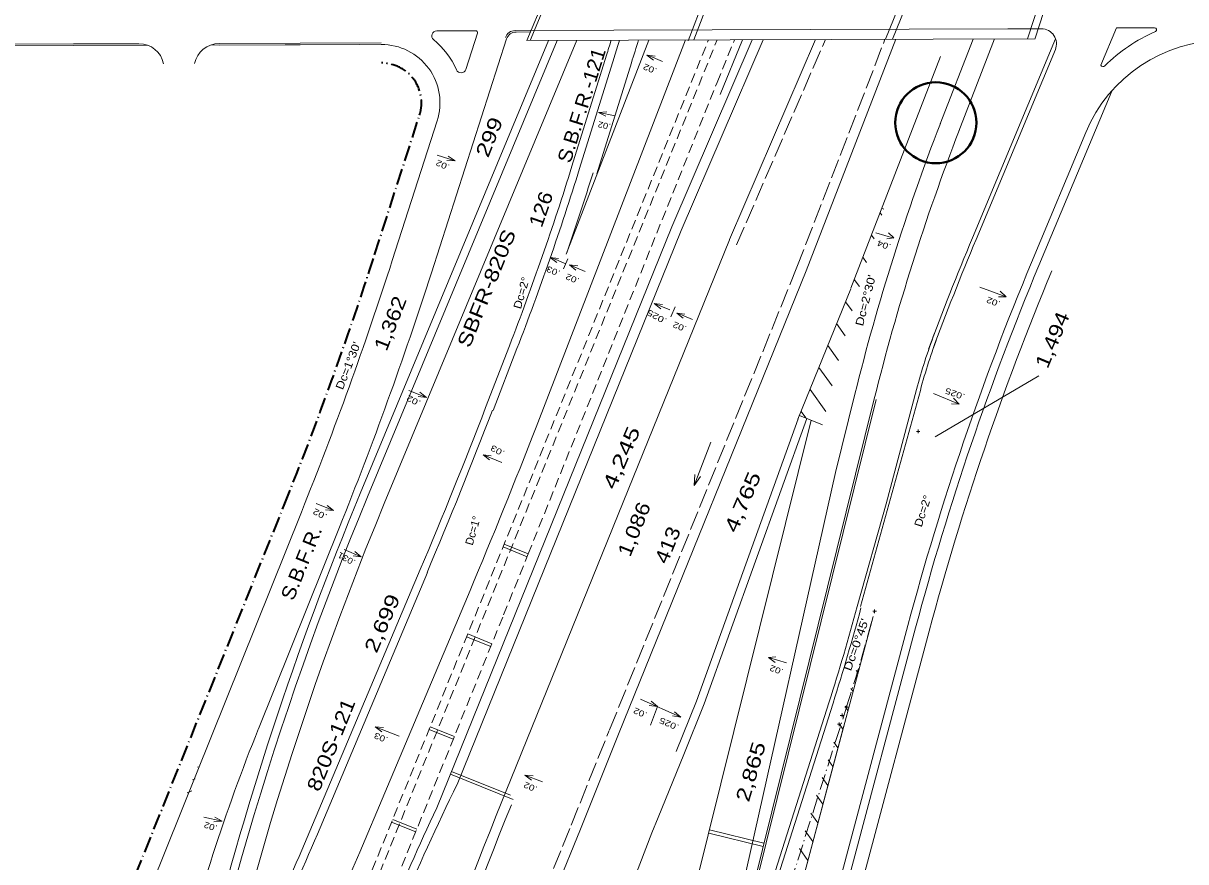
# Model space of a CAD drawing. Extents: x 2354993 to 2372084, y 6966390 to 6990057.
# Drawn here: x 2364225 to 2365387, y 6979642 to 6980481 of the extents above; entities that cross this region are included whole.
import ezdxf

# ---------------------------------------------------------------- set-up
doc = ezdxf.new("R2010")
doc.units = 0
doc.header["$LTSCALE"] = 3.2
for name, pattern in [('DOT_DASHED', [7.7, 5, -1.2, 0.3, -1.2]), ('LONG_DASHED', [7.5, 6, -1.5]), ('MEDIUM_DASHED', [4.5, 3, -1.5])]:
    doc.linetypes.add(name, pattern=pattern)
for name, color, linetype, lineweight in [('1', 7, 'Continuous', 35), ('12', 7, 'Continuous', 13), ('13', 7, 'Continuous', 13), ('14', 7, 'Continuous', 13), ('17', 7, 'Continuous', 13), ('19', 7, 'Continuous', 13), ('23', 7, 'Continuous', 13), ('25', 7, 'Continuous', 13), ('4', 7, 'Continuous', 13), ('5', 7, 'Continuous', 13), ('6', 7, 'Continuous', 13), ('61', 7, 'Continuous', 13), ('7', 7, 'Continuous', 13), ('9', 7, 'Continuous', 13)]:
    doc.layers.add(name, color=color, linetype=linetype, lineweight=lineweight)

msp = doc.modelspace()

# ---------------------------------------------------------------- linework, layer by layer
at = {"layer": '1', "lineweight": 40}
msp.add_circle((2365136.989, 6980381.3), 40.519, dxfattribs=at)
at = {"layer": '12'}
for p, q in [((2364889.34, 6980463.063), (2364934.323, 6980581.712)), ((2364895.069, 6980464.071), (2364938.998, 6980579.939)), ((2365133.691, 6980580.838), (2365086.673, 6980464.691)), ((2365140.767, 6980580.861), (2365093.748, 6980464.714)), ((2365263.831, 6980574.448), (2365228.608, 6980465.09)), ((2365273.39, 6980581.292), (2365235.902, 6980464.902)), ((2364704.438, 6979956.949), (2364728.538, 6979947.192)), ((2364668.081, 6979867.134), (2364692.181, 6979857.378)), ((2364669.206, 6979869.916), (2364693.307, 6979860.159)), ((2364630.558, 6979774.44), (2364654.658, 6979764.684)), ((2364631.683, 6979777.222), (2364655.784, 6979767.465)), ((2364714.411, 6979704.364), (2364651.877, 6979729.644)), ((2364711.823, 6979708.645), (2364653.001, 6979732.425)), ((2364593.035, 6979681.747), (2364617.135, 6979671.991)), ((2364594.16, 6979684.529), (2364618.261, 6979674.773))]:
    msp.add_line(p, q, dxfattribs=at)
at = {"layer": '13'}
for p, q in [((2365036.612, 6980031.444), (2365056.061, 6980109.786)), ((2364922.585, 6979522.917), (2365036.612, 6980031.444))]:
    msp.add_line(p, q, dxfattribs=at)
msp.add_arc((2362792.03, 6980397.361), 1919.859, 325.95112, 337.15034, dxfattribs=at)
at = {"layer": '14'}
msp.add_line((2364895.323, 6980018.418), (2364901.939, 6980027.303), dxfattribs=at)
msp.add_lwpolyline([(2364912.252, 6980061.865), (2364895.323, 6980018.418), (2364896.266, 6980029.456)], dxfattribs=at)
at = {"layer": '17'}
for p, q in [((2365095.189, 6980265.952), (2365077.196, 6980271.228)), ((2365095.104, 6980266.029), (2365089.771, 6980271.008)), ((2365094.987, 6980266.028), (2365088.195, 6980265.248)), ((2364969.717, 6979846.32), (2364977.167, 6979846.989)), ((2364561.233, 6979651.852), (2364586.145, 6979710.973))]:
    msp.add_line(p, q, dxfattribs=at)
msp.add_lwpolyline([(2364987.709, 6979841.045), (2364969.716, 6979846.321), (2364976.272, 6979841.429)], dxfattribs=at)
at = {"layer": '19'}
for p, q in [((2364848.319, 6980448.928), (2364854.815, 6980443.747)), ((2364848.319, 6980448.928), (2364856.571, 6980447.946)), ((2364863.906, 6980442.526), (2364849.11, 6980448.709)), ((2364799.753, 6980391.639), (2364808.048, 6980392.134)), ((2364799.753, 6980391.639), (2364807.064, 6980387.691)), ((2364816.228, 6980388.1), (2364800.57, 6980391.564)), ((2364638.595, 6980348.957), (2364656.429, 6980343.169)), ((2364656.429, 6980343.169), (2364648.126, 6980343.473)), ((2364656.429, 6980343.169), (2364649.532, 6980347.801)), ((2364751.674, 6980246.584), (2364758.17, 6980241.403)), ((2364751.674, 6980246.584), (2364759.926, 6980245.602)), ((2364767.261, 6980240.182), (2364752.465, 6980246.365)), ((2364769.185, 6980245.227), (2364764.875, 6980235.276)), ((2364770.828, 6980238.995), (2364777.324, 6980233.814)), ((2364770.828, 6980238.995), (2364779.08, 6980238.013)), ((2364786.415, 6980232.593), (2364771.619, 6980238.776)), ((2364855.541, 6980200.419), (2364862.037, 6980195.238)), ((2364855.541, 6980200.419), (2364863.793, 6980199.437)), ((2364871.128, 6980194.017), (2364856.332, 6980200.2)), ((2365207.175, 6980207.287), (2365199.555, 6980207.167)), ((2364876.405, 6980197.169), (2364872.095, 6980187.218)), ((2364878.048, 6980190.937), (2364884.544, 6980185.756)), ((2364878.048, 6980190.937), (2364886.3, 6980189.955)), ((2364893.635, 6980184.535), (2364878.839, 6980190.718)), ((2364610.341, 6980113.456), (2364627.785, 6980106.582)), ((2364627.785, 6980106.582), (2364619.516, 6980107.397)), ((2364627.785, 6980106.582), (2364621.186, 6980111.63)), ((2365160.351, 6980099.839), (2365152.732, 6980099.987)), ((2364684.446, 6980049.11), (2364692.709, 6980048.216)), ((2364517.739, 6980000.366), (2364535.115, 6979993.323)), ((2364535.115, 6979993.323), (2364526.855, 6979994.218)), ((2364535.115, 6979993.323), (2364528.565, 6979998.435)), ((2364545.495, 6979954.387), (2364562.777, 6979947.116)), ((2364562.777, 6979947.116), (2364554.529, 6979948.119)), ((2364562.777, 6979947.116), (2364556.295, 6979952.313)), ((2364858.74, 6979797.296), (2364850.508, 6979798.436)), ((2364851.801, 6979778.744), (2364858.845, 6979797.443)), ((2364858.74, 6979797.296), (2364852.347, 6979802.598)), ((2364882.037, 6979786.826), (2364873.805, 6979787.966)), ((2364576.617, 6979777.045), (2364584.89, 6979776.258)), ((2364726.287, 6979728.711), (2364734.566, 6979728)), ((2364405.503, 6979686.85), (2364423.765, 6979682.602)), ((2364423.765, 6979682.602), (2364415.466, 6979682.198)), ((2364423.765, 6979682.602), (2364416.498, 6979686.63))]:
    msp.add_line(p, q, dxfattribs=at)
for points in [[(2365181.045, 6980216.968), (2365207.175, 6980207.287), (2365201.372, 6980212.914)], [(2365134.575, 6980110.427), (2365160.351, 6980099.839), (2365154.747, 6980105.667)], [(2364703.322, 6980041.457), (2364684.446, 6980049.11), (2364690.995, 6980044)], [(2364841.954, 6979804.669), (2364882.037, 6979786.826), (2364875.644, 6979792.128)], [(2364600.634, 6979767.668), (2364576.617, 6979777.045), (2364583.231, 6979772.021)], [(2364743.816, 6979722.055), (2364726.287, 6979728.711), (2364732.949, 6979723.746)]]:
    msp.add_lwpolyline(points, dxfattribs=at)
at = {"layer": '23'}
msp.add_line((2365023.63, 6979472.53), (2365130.321, 6979872.599), dxfattribs=at)
msp.add_arc((2367865.518, 6979143.17), 2830.789, 157.35649, 165.06774, dxfattribs=at)
at = {"layer": '25'}
for p, q in [((2364638.192, 6980473.229), (2364676.956, 6980473.353)), ((2364678.866, 6980470.741), (2364667.27, 6980434.672)), ((2364716.429, 6980473.483), (2365209.079, 6980475.077)), ((2364717.51, 6980471.986), (2364731.864, 6980472.033)), ((2364758.63, 6980463.629), (2364569.087, 6980007.233)), ((2364632.777, 6980231.022), (2364708.023, 6980465.047)), ((2364767.688, 6980249.927), (2364850.216, 6980463.926)), ((2364882.46, 6980273.331), (2364964.36, 6980464.295)), ((2364930.859, 6980264.426), (2365016.654, 6980464.464)), ((2365007.434, 6980233.06), (2365096.929, 6980464.724)), ((2365256.568, 6980465.111), (2365173.563, 6980266.128)), ((2364780.996, 6980335.421), (2364815.568, 6980446.589)), ((2365052.209, 6980215.763), (2365141.704, 6980447.427)), ((2364593.745, 6980243.573), (2364638.621, 6980383.141)), ((2365083.088, 6980295.695), (2365084.953, 6980294.974)), ((2364658.462, 6979719.253), (2364882.46, 6980273.331)), ((2364697.647, 6979688.336), (2364930.731, 6980264.109)), ((2365007.434, 6980233.06), (2364819.815, 6979769.595)), ((2365051.927, 6980215.049), (2364999.207, 6980084.818)), ((2364694.499, 6980093.497), (2364718.352, 6980155.347)), ((2365121.023, 6980072.57), (2365117.523, 6980072.57)), ((2365119.273, 6980074.32), (2365119.273, 6980070.82)), ((2364345.135, 6979599.119), (2364502.883, 6979991.918)), ((2364459.929, 6979774.94), (2364540.926, 6979976.626)), ((2364518.842, 6979669.717), (2364629.05, 6979931.257)), ((2365077.464, 6979892.584), (2365073.964, 6979892.584)), ((2365077.556, 6979892.776), (2365074.056, 6979892.776)), ((2365077.556, 6979892.776), (2365074.056, 6979892.776)), ((2365077.556, 6979892.776), (2365074.056, 6979892.776)), ((2365075.714, 6979894.334), (2365075.714, 6979890.834)), ((2365075.806, 6979894.526), (2365075.806, 6979891.026)), ((2365075.806, 6979894.526), (2365075.806, 6979891.026)), ((2365075.806, 6979894.526), (2365075.806, 6979891.026)), ((2365049.425, 6979796.588), (2365045.925, 6979796.588)), ((2365047.675, 6979798.338), (2365047.675, 6979794.838)), ((2365040.342, 6979781.355), (2365040.342, 6979777.855)), ((2365044.976, 6979788.49), (2365041.476, 6979788.49)), ((2365044.976, 6979788.49), (2365041.476, 6979788.49)), ((2365043.226, 6979790.24), (2365043.226, 6979786.74)), ((2365043.226, 6979790.24), (2365043.226, 6979786.74)), ((2364781.72, 6979674.823), (2364819.815, 6979769.595)), ((2365042.092, 6979779.605), (2365038.592, 6979779.605)), ((2364746.17, 6979587.006), (2364781.72, 6979674.823))]:
    msp.add_line(p, q, dxfattribs=at)
at = {"layer": '25', "linetype": 'LONG_DASHED'}
for p, q in [((2364937.909, 6980259.273), (2365026.649, 6980464.497)), ((2364998.106, 6980236.664), (2365086.195, 6980464.689)), ((2364998.165, 6980236.812), (2364810.546, 6979773.347)), ((2364772.442, 6979678.553), (2364810.537, 6979773.325)), ((2364736.901, 6979590.758), (2364772.451, 6979678.575))]:
    msp.add_line(p, q, dxfattribs=at)
at = {"layer": '25'}
for centre, radius, start, end in [((2364638.208, 6980468.229), 5, 90.18352, 230.55088), ((2364676.962, 6980471.353), 2, 342.17766, 90.18286), ((2364716.461, 6980463.483), 10, 90.18543, 162.29546), ((2364717.543, 6980461.986), 10, 90.18655, 162.17584), ((2364582.929, 6980401.048), 58.5, 342.17569, 90.18757), ((2364582.928, 6980401.048), 82, 23.83292, 50.55088), ((2370300.051, 6978740.971), 5743.578, 162.54462, 162.72484), ((2364662.51, 6980436.202), 5, 203.83292, 342.17739), ((2362045.437, 6981186.146), 2864.789, 338.91107, 342.72496), ((2362045.437, 6981186.146), 2878.788, 341.04639, 342.72496), ((2367865.717, 6979143.099), 2917, 157.35659, 159.70903), ((2360994.978, 6981400.695), 3780.219, 338.11957, 342.17569), ((2360994.975, 6981400.684), 3821.219, 338.11954, 342.17584), ((2365704.789, 6979956.656), 608, 159.3693, 164.95986), ((2359382.264, 6982142.156), 5693.004, 337.15034, 338.91091), ((2367605.673, 6978746.13), 3288.045, 157.44674, 182.51497), ((2366230.85, 6979063.738), 1908.395, 158.10759, 166.15522), ((2366552.173, 6978785.649), 2111.37, 153.74294, 161.2917), ((2367353.101, 6978613.358), 2864.789, 157.96096, 179.2503), ((2362792.03, 6980397.363), 1873.859, 329.95811, 337.15034)]:
    msp.add_arc(centre, radius, start, end, dxfattribs=at)
at = {"layer": '4'}
for p, q in [((2364749.956, 6980463.601), (2364561.699, 6980010.301)), ((2364778.146, 6980463.692), (2364585.71, 6980000.329)), ((2364737.418, 6980076.945), (2364886.702, 6980464.044)), ((2364773.357, 6980337.797), (2364807.929, 6980448.965)), ((2364798.185, 6980330.076), (2364832.756, 6980441.239)), ((2364687.035, 6980096.375), (2364710.887, 6980158.227)), ((2364511.47, 6979672.823), (2364621.678, 6979934.363)), ((2364586.141, 6979710.964), (2364671.441, 6979913.394))]:
    msp.add_line(p, q, dxfattribs=at)
for centre, radius, start, end in [((2370300.051, 6978740.971), 5751.578, 162.56997, 162.72484), ((2370300.048, 6978740.957), 5725.578, 162.48367, 162.72475), ((2362045.437, 6981186.146), 2856.789, 338.91107, 342.72496), ((2359382.264, 6982142.156), 5685.578, 337.15034, 338.91091), ((2359382.265, 6982142.155), 5739.578, 337.15034, 338.91091), ((2367605.673, 6978746.13), 3296.044, 157.44674, 174.9586), ((2367605.673, 6978746.13), 3270.045, 157.44674, 184.53246), ((2362792.03, 6980397.363), 1865.859, 330.35581, 337.15034)]:
    msp.add_arc(centre, radius, start, end, dxfattribs=at)
at = {"layer": '5'}
for p, q in [((2364776.569, 6980579.679), (2364728.333, 6980463.531)), ((2364779.822, 6980579.689), (2364731.586, 6980463.541)), ((2365209.08, 6980475.089), (2365242.552, 6980475.198)), ((2365317.549, 6980476.192), (2365301.926, 6980438.711)), ((2365317.549, 6980476.192), (2365355.639, 6980476.315)), ((2364212.913, 6980459.849), (2364275.143, 6980460.051)), ((2364212.918, 6980458.349), (2364275.148, 6980458.551)), ((2364275.143, 6980460.041), (2364340.584, 6980460.255)), ((2364275.148, 6980458.541), (2364349.118, 6980458.783)), ((2364412.06, 6980458.989), (2364561.033, 6980459.477)), ((2364420.584, 6980460.517), (2364582.732, 6980461.048)), ((2364420.589, 6980459.017), (2364582.737, 6980459.548)), ((2364728.333, 6980463.531), (2365235.989, 6980465.174)), ((2364873.225, 6980277.168), (2364953.464, 6980464.26)), ((2364921.552, 6980409.674), (2364943.79, 6980464.228)), ((2365141.413, 6980380.074), (2365174.211, 6980464.974)), ((2365160.069, 6980372.867), (2365195.679, 6980465.044)), ((2365256.444, 6980454.423), (2365177.254, 6980264.588)), ((2365240.01, 6980238.403), (2365312.776, 6980412.838)), ((2365232.627, 6980241.483), (2365286.877, 6980371.531)), ((2365081.383, 6980291.281), (2365083.112, 6980288.869)), ((2364638.255, 6979695.95), (2364873.225, 6980277.167)), ((2365072.766, 6980268.977), (2365075.393, 6980265.315)), ((2365064.15, 6980246.673), (2365067.869, 6980241.487)), ((2365055.534, 6980224.369), (2365060.547, 6980217.379)), ((2365046.76, 6980202.285), (2365053.43, 6980192.984)), ((2365037.88, 6980180.349), (2365046.525, 6980168.294)), ((2365029, 6980158.413), (2365039.837, 6980143.302)), ((2365020.12, 6980136.477), (2365033.372, 6980117.998)), ((2365239.993, 6980127.96), (2365136.183, 6980067.213)), ((2365011.24, 6980114.541), (2365027.042, 6980092.506)), ((2365061.659, 6979897.318), (2365121.53, 6980113.58)), ((2365087.473, 6980000.245), (2365117.617, 6980114.429)), ((2364760.631, 6978828.473), (2365077.413, 6980104.485)), ((2364952, 6979607.617), (2365075.472, 6980104.967)), ((2364704.339, 6978842.448), (2365012.522, 6980083.82)), ((2364897.947, 6979802.7), (2364999.406, 6980085.023)), ((2364905.475, 6979799.995), (2365008.116, 6980085.603)), ((2365000.735, 6980088.591), (2365023.757, 6980079.271)), ((2365002.36, 6980092.605), (2365007.081, 6980086.022)), ((2365058.33, 6979897.253), (2365087.473, 6980000.245)), ((2364705.563, 6979959.728), (2364729.664, 6979949.972)), ((2364967.588, 6979487.475), (2365074.28, 6979887.544)), ((2365002.373, 6979478.198), (2365109.064, 6979878.268)), ((2365010.102, 6979476.137), (2365116.794, 6979876.206)), ((2365057.509, 6979833.455), (2365059.219, 6979831.07)), ((2365051.935, 6979815.488), (2365054.216, 6979812.308)), ((2364897.947, 6979802.7), (2364877.608, 6979752.459)), ((2364905.475, 6979799.995), (2364885.023, 6979749.457)), ((2365046.328, 6979797.568), (2365049.212, 6979793.546)), ((2364967.588, 6979487.475), (2365045.124, 6979778.215)), ((2365040.687, 6979779.694), (2365044.209, 6979774.784)), ((2365035.013, 6979761.868), (2365039.205, 6979756.022)), ((2364859.546, 6979686.522), (2364885.023, 6979749.457)), ((2364398.923, 6979736.776), (2364399.85, 6979737.154)), ((2365029.293, 6979744.104), (2365034.202, 6979737.26)), ((2364393.979, 6979723.958), (2364396.661, 6979725.052)), ((2365023.561, 6979726.358), (2365029.198, 6979718.498)), ((2364388.889, 6979711.081), (2364393.519, 6979712.97)), ((2365017.829, 6979708.612), (2365024.195, 6979699.736)), ((2365012.097, 6979690.867), (2365019.191, 6979680.974)), ((2365006.365, 6979673.121), (2365014.188, 6979662.212)), ((2365000.633, 6979655.375), (2365009.184, 6979643.45))]:
    msp.add_line(p, q, dxfattribs=at)
at = {"layer": '5', "linetype": 'MEDIUM_DASHED'}
for p, q in [((2364568.363, 6979620.801), (2364909.746, 6980464.118)), ((2364575.778, 6979617.799), (2364918.388, 6980464.146)), ((2364918.426, 6980421.599), (2364935.672, 6980464.202)), ((2364729.664, 6979949.972), (2364918.426, 6980421.599)), ((2364705.011, 6979889.07), (2364729.664, 6979949.972)), ((2364592.464, 6979611.045), (2364705.011, 6979889.07))]:
    msp.add_line(p, q, dxfattribs=at)
at = {"layer": '5'}
for points in [[(2364881.181, 6979319.258), (2364881.205, 6979319.336), (2365034.333, 6979800.831), (2365034.325, 6979800.806)], [(2364892.613, 6979368.406), (2365030.521, 6979802.044), (2365030.511, 6979802.011)]]:
    msp.add_lwpolyline(points, dxfattribs=at)
for centre, radius, start, end in [((2365242.6, 6980460.198), 15, 337.35659, 90.1868), ((2365426.231, 6980315.276), 172, 113.9326, 134.42167), ((2365355.646, 6980474.316), 2, 293.9326, 90.18471), ((2364340.666, 6980435.255), 25, 11.74837, 90.18759), ((2364420.666, 6980435.517), 25, 90.18759, 168.62957), ((2365425.314, 6980313.781), 150, 90.18714, 157.35649), ((2365304.128, 6980439.894), 2.5, 205.05729, 317.64101), ((2367257.079, 6979563.363), 2267.831, 158.87757, 166.05765), ((2367257.079, 6979563.363), 2247.831, 158.87757, 166.05765), ((2367865.717, 6979143.099), 2913, 157.35659, 159.70501), ((2367865.518, 6979143.17), 2852.789, 157.35649, 165.06774), ((2367865.518, 6979143.17), 2844.789, 157.35649, 165.06774), ((2365700.977, 6979957.883), 600, 159.37414, 164.95986), ((2362862.313, 6980487.013), 2273.831, 342.46704, 344.96741), ((2362862.313, 6980487.013), 2277.831, 342.46704, 344.96741), ((2367353.101, 6978613.358), 2854.789, 157.64771, 178.29047), ((2366552.173, 6978785.649), 2119.37, 154.56326, 161.2917), ((2367632.916, 6978563.811), 2992, 157.9609, 178.42915)]:
    msp.add_arc(centre, radius, start, end, dxfattribs=at)
at = {"layer": '6', "linetype": 'DOT_DASHED', "lineweight": 35}
for p, q in [((2364576.133, 6980249.236), (2364621.009, 6980388.804)), ((2364327.968, 6979606.013), (2364485.716, 6979998.812))]:
    msp.add_line(p, q, dxfattribs=at)
at = {"layer": '6', "linetype": 'DOT_DASHED'}
msp.add_line((2364894.547, 6979315.093), (2365047.675, 6979796.588), dxfattribs=at)
at = {"layer": '6', "linetype": 'DOT_DASHED', "lineweight": 35}
for centre, radius, start, end in [((2364582.929, 6980401.048), 40, 342.17569, 90.18757), ((2360994.978, 6981400.695), 3761.719, 338.11957, 342.17569)]:
    msp.add_arc(centre, radius, start, end, dxfattribs=at)
at = {"layer": '6', "linetype": 'DOT_DASHED'}
msp.add_arc((2362862.313, 6980487.013), 2291.831, 342.46704, 344.96741, dxfattribs=at)
at = {"layer": '61'}
for p, q in [((2364909.973, 6979670.748), (2364964.323, 6979657.255)), ((2364910.816, 6979674.145), (2364965.166, 6979660.652))]:
    msp.add_line(p, q, dxfattribs=at)
at = {"layer": '9'}
msp.add_arc((2360722.521, 6984327.136), 5729.573, 359.50797, 359.50797, dxfattribs=at)

# ---------------------------------------------------------------- texts
at = {"layer": '13'}
for s, rotation, width, p in [('S.B.F.R.-121', 72.597, 1.1, (2364771.772, 6980339.891)), ('299', 68.045, 1.3, (2364689.513, 6980345.521)), ('126', 70.784, 1.15, (2364743.036, 6980275.514)), ('SBFR-820S', 68.045, 1.25, (2364671.074, 6980155.164)), ('1,362', 68.675, 1.2, (2364588.006, 6980151.93)), ('1,494', 67.399, 1.25, (2365248.635, 6980134.416)), ('4,245', 66.79, 1.4, (2364816.252, 6980013.358)), ('4,765', 66.79, 1.35, (2364937.849, 6979970.148)), ('1,086', 68.045, 1.2, (2364831.45, 6979946.104)), ('S.B.F.R.', 67.932, 1.1, (2364494.763, 6979902.309)), ('413', 68.045, 1.2, (2364868.422, 6979938.929)), ('2,699', 66.79, 1.3, (2364578.039, 6979849.891)), ('820S-121', 68.045, 1.2, (2364520.775, 6979711.291)), ('2,865', 73.545, 1.3, (2364950.088, 6979701.037))]:
    msp.add_text(s, height=14, rotation=rotation, dxfattribs=dict(at, width=width)).set_placement(p)
at = {"layer": '17'}
for s, height, rotation, width, p in [('.04', 6, 159.81, 1.25, (2365092.825, 6980259.286)), ('Dc=2°', 8, 74.075, 1.1, (2364722.249, 6980194.391)), ("Dc=2°30'", 8, 75.548, 1.2, (2365064.143, 6980177.299)), ("Dc=1°30'", 8, 68.676, 1.15, (2364544.242, 6980113.558)), ("Dc=0°45'", 8, 70.548, 1.25, (2365052.084, 6979832.294)), ('.02', 6, 159.81, 1.25, (2364985.344, 6979834.38))]:
    msp.add_text(s, height=height, rotation=rotation, dxfattribs=dict(at, width=width)).set_placement(p)
msp.add_text('Dc=1°', height=8, rotation=74.075, dxfattribs=at).set_placement((2364674.079, 6979958.021))
at = {"layer": '19'}
for s, height, rotation, width, p in [('.02', 6, 157.459, 1.25, (2364858.898, 6980435.228)), ('.02', 6, 167.664, 1.15, (2364812.592, 6980380.03)), ('.02', 5.999, 156.625, 1.25, (2364651.739, 6980338.969)), ('.03', 6, 157.459, 1.25, (2364762.253, 6980232.884)), ('.02', 6, 157.459, 1.25, (2364781.407, 6980225.295)), ('.02', 6, 158.402, 1.25, (2365202.083, 6980202.224)), ('.025', 6, 151.78, 1.35, (2364868.851, 6980184.837)), ('.02', 6, 157.459, 1.25, (2364888.627, 6980177.237)), ('.02', 5.999, 153.098, 1.3, (2364622.846, 6980102.679)), ('.025', 6, 160.402, 1.3, (2365166.754, 6980109.548)), ('.03', 6, 152.03, 1.3, (2364706.812, 6980052.483)), ('.02', 5.999, 152.545, 1.3, (2364529.292, 6979989.097)), ('.031', 5.999, 151.789, 1.2, (2364557.75, 6979943.327)), ('.02', 6, 156.266, 1.25, (2364849.102, 6979790.993)), ('.025', 6, 156.502, 1.3, (2364880.917, 6979778.65)), ('.03', 6, 157.497, 1.25, (2364590.035, 6979766.221)), ('.02', 5.999, 156.361, 1.25, (2364739.411, 6979716.782)), ('.02', 5.999, 161.512, 1.2, (2364419.45, 6979678.019))]:
    msp.add_text(s, height=height, rotation=rotation, dxfattribs=dict(at, width=width)).set_placement(p)
at = {"layer": '7', "width": 1.1}
msp.add_text('Dc=2°', height=7.999, rotation=72.088, dxfattribs=at).set_placement((2365122.773, 6979976.265))

doc.saveas('drawing.dxf')
